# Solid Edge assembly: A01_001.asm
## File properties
Author: mokuno
Template: Jis Assembly.asm
Last saved by: edge
Revision: 31
Application: Solid Edge
文書内容のタイプ: 1
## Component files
A01_roller.par
A01_Splate.par
A01_chead.par
A01_bolt.par
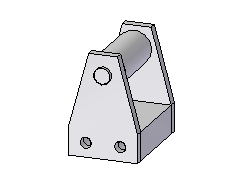
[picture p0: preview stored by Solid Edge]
